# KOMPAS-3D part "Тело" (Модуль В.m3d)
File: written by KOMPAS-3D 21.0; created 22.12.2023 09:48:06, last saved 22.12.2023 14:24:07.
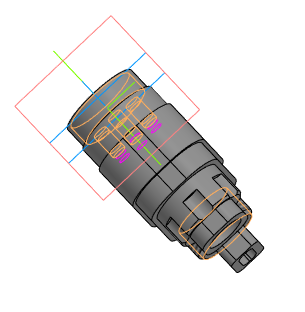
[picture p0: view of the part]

Document properties: Полное имя файла: D:\ГЛАВНЮК\ГЭ Москвы\Регион 2023-24\КД 2024 РЧ\Юниоры\КЗ\ВЗРОСЛЫЕ\проба взросл.m3d; Автор: Админ

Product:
- Part/product: Тело
    Масса: 0.901045
    Форматы листов документа: A3
  - Body: Тело 1
      Масса: 0.932078

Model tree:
1. Операция без истории:1
2. Условное изображение резьбы:5  (with: Операция без истории:1)  (labels: M30x1,5; cil0_24705-2004 fine)
     Длина резьбы = 9; Шаг резьбы = 1.5; Номинальный диаметр резьбы = 30
3. Подгонка:5  (with: Операция без истории:1)
4. Эскиз:1  (with: Операция без истории:1)
5. Элемент выдавливания:1
     Расстояние 2 = 5
6. Эскиз:2  (with: Операция без истории:1)
7. Придать толщину:1  (with: Операция без истории:1)
     Толщина стенки 1 = 3
8. Эскиз:4  (with: Операция без истории:1)
9. Элемент выдавливания:3
     Расстояние 2 = 10
10. Эскиз:5  (with: Операция без истории:1)
11. Элемент выдавливания:4
     Расстояние 2 = 5
12. Элемент выдавливания:5  (with: Операция без истории:1)
     Расстояние 2 = 4
13. Эскиз:8  (with: Операция без истории:1)
14. Отверстие:7  (with: Операция без истории:1)
     Глубина выреза = 12; Диаметр отверстия = 5; Угол конуса дна = 118; Расстояние 1 = 8.22724; Расстояние 2 = 15.25
15. Эскиз:9  (with: Операция без истории:1)
16. Отверстие:8
     Глубина выреза = 1; Диаметр отверстия = 5; Угол конуса дна = 118; Расстояние 2 = 10.5
17. Эскиз:10  (with: Операция без истории:1)
18. Отверстие:9
     Глубина выреза = 1; Диаметр отверстия = 5; Угол конуса дна = 118; Расстояние 1 = -8.22724; Расстояние 2 = 15.25
19. Эскиз:11  (with: Операция без истории:1)
20. Отверстие:10
     Глубина выреза = 1; Диаметр отверстия = 5; Угол конуса дна = 118; Расстояние 1 = -8.22724; Расстояние 2 = 24.75
21. Эскиз:13  (with: Операция без истории:1)
22. Отверстие:11
     Глубина выреза = 1; Диаметр отверстия = 5; Угол конуса дна = 118; Расстояние 2 = 29.5
23. Эскиз:14  (with: Операция без истории:1)
24. Отверстие:12
     Глубина выреза = 1; Диаметр отверстия = 5; Угол конуса дна = 118; Расстояние 1 = 8.22724; Расстояние 2 = 24.75
25. Условное изображение резьбы:12  (with: Операция без истории:1, Отверстие:7)  (labels: M6; cil0_24705-2004 coarse)
     Длина резьбы = 9; Шаг резьбы = 1; Номинальный диаметр резьбы = 6
26. Подгонка:7  (with: Отверстие:7, Операция без истории:1)
27. Условное изображение резьбы:13  (with: Операция без истории:1)  (labels: M6; cil0_24705-2004 coarse)
     Длина резьбы = 9; Шаг резьбы = 1; Номинальный диаметр резьбы = 6
28. Подгонка:8  (with: Отверстие:8, Операция без истории:1)
29. Условное изображение резьбы:14  (with: Операция без истории:1)  (labels: M6; cil0_24705-2004 coarse)
     Длина резьбы = 9; Шаг резьбы = 1; Номинальный диаметр резьбы = 6
30. Подгонка:9  (with: Отверстие:9, Операция без истории:1)
31. Условное изображение резьбы:16  (with: Операция без истории:1)  (labels: M6; cil0_24705-2004 coarse)
     Длина резьбы = 9; Шаг резьбы = 1; Номинальный диаметр резьбы = 6
32. Подгонка:11  (with: Отверстие:10, Операция без истории:1)
33. Условное изображение резьбы:17  (with: Операция без истории:1)  (labels: M6; cil0_24705-2004 coarse)
     Длина резьбы = 9; Шаг резьбы = 1; Номинальный диаметр резьбы = 6
34. Подгонка:12  (with: Отверстие:11, Операция без истории:1)
35. Условное изображение резьбы:18  (with: Операция без истории:1)  (labels: M6; cil0_24705-2004 coarse)
     Длина резьбы = 9; Шаг резьбы = 1; Номинальный диаметр резьбы = 6
36. Подгонка:13  (with: Отверстие:12, Операция без истории:1)
37. Придать толщину:4  (with: Операция без истории:1)
     Толщина стенки 1 = 0.4
38. Элемент выдавливания:7
     Расстояние 2 = 7
39. Эскиз:15  (with: Операция без истории:1)
40. Элемент выдавливания:8
     Расстояние 2 = 25
41. Эскиз:16  (with: Операция без истории:1)
42. Элемент выдавливания:9  (with: Операция без истории:1)
     Расстояние 2 = 15
43. Условное изображение резьбы:19  (with: Элемент выдавливания:9)  (labels: M27x2; cil0_24705-2004 fine)
     Длина резьбы = 14; Шаг резьбы = 2; Номинальный диаметр резьбы = 27
44. Подгонка:1  (with: Элемент выдавливания:9)
45. Фаска:1  (with: Элемент выдавливания:9)
     Угол = 45; Длина 1 = 1.5; Длина 2 = 1.5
